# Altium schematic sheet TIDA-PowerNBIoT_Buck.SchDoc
size 431 x 279 mm; Date: Not shown in title block; ApprovedBy: Not shown in title block; CheckedBy: Not shown in title block; Author: Not shown in title block; CompanyName: Not shown in title block; DrawnBy: Chris Glaser; Engineer: Not shown in title block; Organization: Not shown in title block; Address1: Not shown in title block; Address2: Not shown in title block; Address3: Not shown in title block; Address4: Not shown in title block; DocumentNumber: 1; Revision: Use project parameter SCH_Rev; SheetNumber: 1; SheetTotal: 2; PageSetup: Record=PageOptions¦CenterHorizontal=True¦CenterVertical=True¦PrintScale=1.00¦XCorrection=1.00¦YCorrection=1.00¦PrintKind=0¦BorderSize=5000000¦LeftOffset=0¦BottomOffset=0¦Orientation=2¦PaperLength=1000¦PaperWidth=1000¦Scale=100¦PaperSource=15¦PrintQuality=600¦MediaType=1¦DitherType=10¦PaperKind=Letter¦PrintScaleMode=1
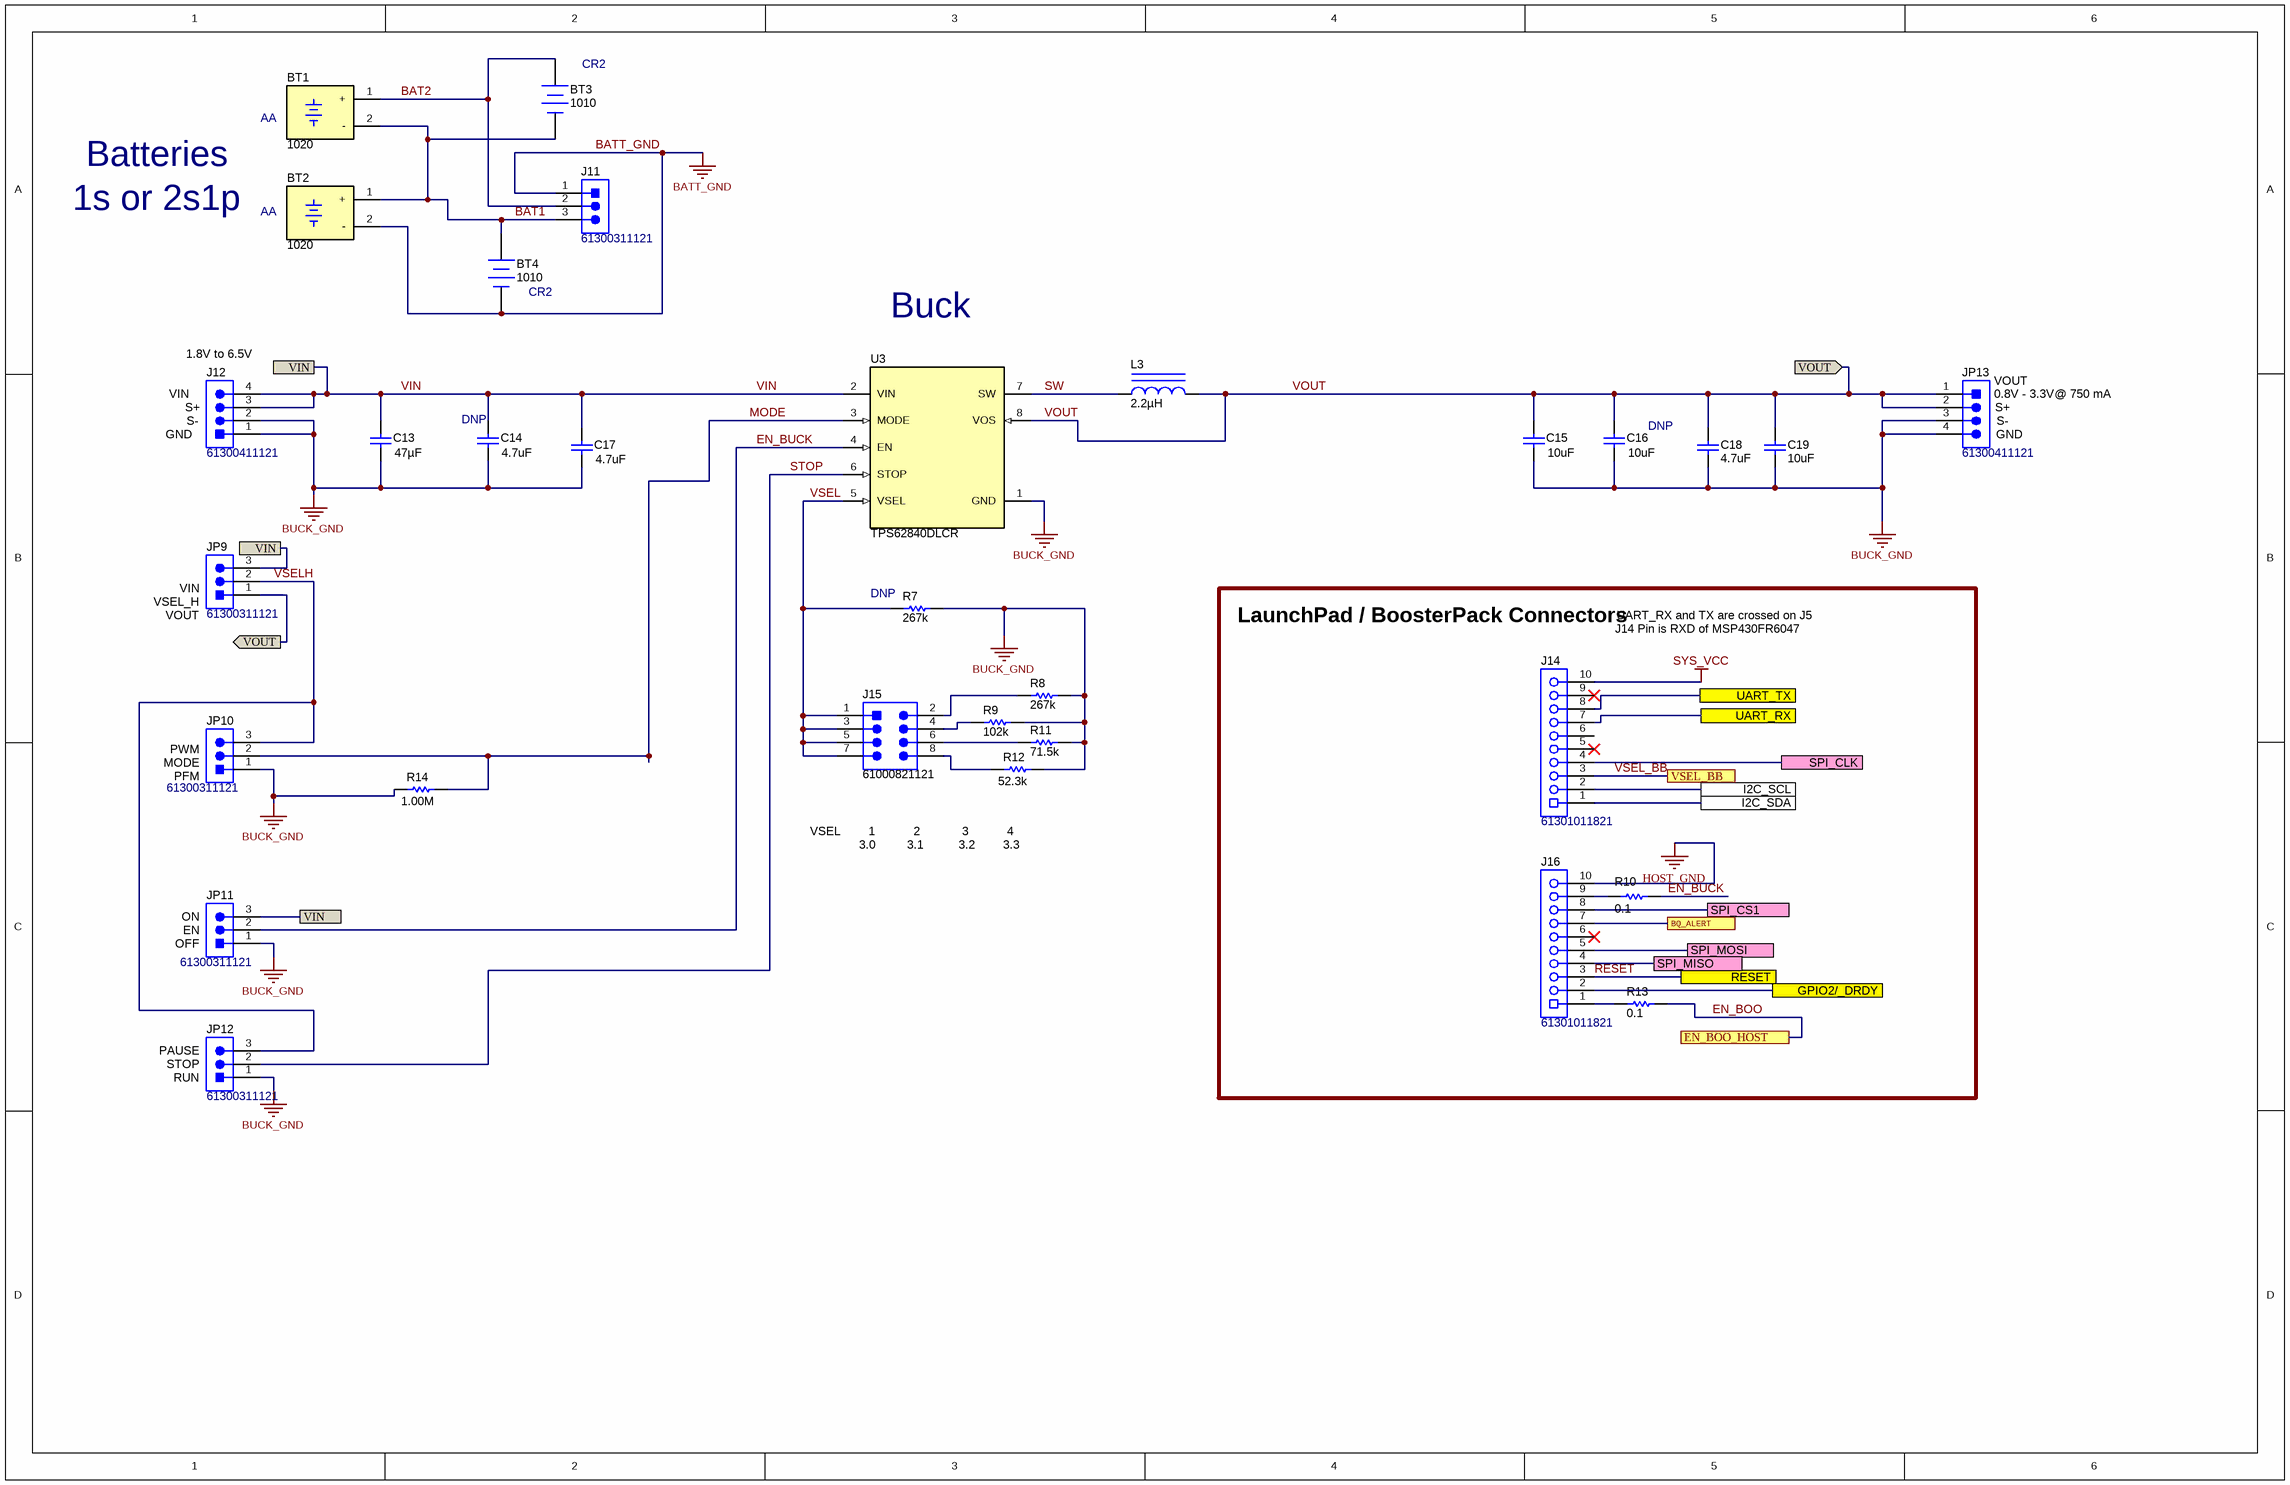
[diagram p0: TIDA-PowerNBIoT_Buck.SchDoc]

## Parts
BT1  1020  [Keystone_1020]
BT2  1020  [Keystone_1020]
BT3  1010  [BAT_1010]
BT4  1010  [BAT_1010]
C13  ValueDisplayed: 47µF  [0805_HV]  (hidden comment: GRM21BR61A476ME15L)
C14  ValueDisplayed: 4.7uF  [0402S]  (hidden comment: GRM155R61A475MEAAD)
C15  ValueDisplayed: 10uF  [0402_070]  (hidden comment: GRM155R60G106ME44D)
C16  ValueDisplayed: 10uF  [0402_070]  (hidden comment: GRM155R60G106ME44D)
C17  ValueDisplayed: 4.7uF  [0402S]  (hidden comment: GRM155R61A475MEAAD)
C18  ValueDisplayed: 4.7uF  [0603S]  (hidden comment: GRM188R60J475ME19D)
C19  ValueDisplayed: 10uF  [0805_HV]  (hidden comment: GRM21BR70J106KE76L)
J11  61300311121  [WURTH_61300311121]
J12  61300411121  [WURTH_61300411121]
J14  61301011821  [Wurth_61301011821]
J15  61000821121  [Wurth_61000821121]
J16  61301011821  [Wurth_61301011821]
JP9  61300311121  [WURTH_61300311121]
JP10  61300311121  [WURTH_61300311121]
JP11  61300311121  [WURTH_61300311121]
JP12  61300311121  [WURTH_61300311121]
JP13  61300411121  [WURTH_61300411121]
L3  ValueDisplayed: 2.2µH  [DFE201612E]  (hidden comment: DFE201612E-2R2M=P2)
R7  ValueDisplayed: 267k  [0402]  (hidden comment: ERJ-2RKF2673X)
R8  ValueDisplayed: 267k  [0402]  (hidden comment: ERJ-2RKF2673X)
R9  ValueDisplayed: 102k  [0402]  (hidden comment: CRCW0402102KFKED)
R10  ValueDisplayed: 0.1  [0402]  (hidden comment: ERJ-2BSFR10X)
R11  ValueDisplayed: 71.5k  [0402]  (hidden comment: CRCW040271K5FKED)
R12  ValueDisplayed: 52.3k  [0402]  (hidden comment: CRCW040252K3FKED)
R13  ValueDisplayed: 0.1  [0402]  (hidden comment: ERJ-2BSFR10X)
R14  ValueDisplayed: 1.00M  [0402]  (hidden comment: CRCW04021M00FKED)
U3  TPS62840DLCR  [DLC0008B]

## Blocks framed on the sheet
LaunchPad / BoosterPack Connectors: J14 J16 R10 R13

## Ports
BQ_ALERT, EN_BOO_HOST, GPIO2/_DRDY, I2C_SCL, I2C_SDA, RESET, SPI_CLK, SPI_CS1, SPI_MISO, SPI_MOSI, UART_RX, UART_TX, VIN, VOUT (in), VOUT (out), VSEL_BB

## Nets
BATT_GND: BT2.2(-) BT4.2(-) J11.1
BUCK_GND: C13.2 C14.2 C15.2 C16.2 C17.2 C18.2 C19.2 J12.1 J12.2 JP10.1 JP11.1 JP12.1 JP13.3 JP13.4 R7.2 R8.2 R9.2 R11.2 R12.2 R14.1 U3.1(GND)
HOST_GND: J16.10
SYS_VCC: J14.10
BAT1: BT1.2(-) BT2.1(+) BT3.2(-) BT4.1(+) J11.3
BAT2: BT1.1(+) BT3.1(+) J11.2
BQ_ALERT: J16.7 ; port BQ_ALERT
EN_BOO: R13.2 ; port EN_BOO_HOST
EN_BUCK: JP11.2 R10.2 U3.4(EN)
GPIO2/_DRDY: J16.2 ; port GPIO2/_DRDY
I2C_SCL: J14.2 ; port I2C_SCL
I2C_SDA: J14.1 ; port I2C_SDA
MODE: JP10.2 R14.2 U3.3(MODE)
RESET: J16.3 ; port RESET
SPI_CLK: J14.4 ; port SPI_CLK
SPI_CS1: J16.8 ; port SPI_CS1
SPI_MISO: J16.4 ; port SPI_MISO
SPI_MOSI: J16.5 ; port SPI_MOSI
STOP: JP12.2 U3.6(STOP)
SW: L3.1 U3.7(SW)
UART_RX: J14.7 ; port UART_RX
UART_TX: J14.8 ; port UART_TX
VIN: C13.1 C14.1 C17.1 J12.3 J12.4 JP9.3 JP11.3 U3.2(VIN) ; port VIN
VOUT: C15.1 C16.1 C18.1 C19.1 JP9.1 JP13.1 JP13.2 L3.2 U3.8(VOS) ; port VOUT
VSEL: J15.1 J15.3 J15.5 J15.7 R7.1 U3.5(VSEL)
VSEL_BB: J14.3 ; port VSEL_BB
VSELH: JP9.2 JP10.3 JP12.3
NetJ15_2: J15.2 R8.1
NetJ15_4: J15.4 R9.1
NetJ15_6: J15.6 R11.1
NetJ15_8: J15.8 R12.1
NetJ16_1: J16.1 R13.1
NetJ16_9: J16.9 R10.1

Not connected (* = marked no-connect by the designer): J14 5* 6 9*; J16 6*

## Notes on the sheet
- (near BT3) CR2
- AA
- 1s or 2s1p
- Batteries
- (near BT4) CR2
- (near J12) 1.8V to 6.5V
- Buck
- (near J12) VIN
- (near J12) GND
- (near J12) S+
- (near J12) S-
- (near C14) DNP
- DNP
- (near JP13) S+
- (near JP13) S-
- (near JP13) GND
- (near JP13) VOUT
- (near JP13) 0.8V - 3.3V
- @ 750 mA
- (near JP9) VSEL_H
- (near JP9) VOUT
- (near JP9) VIN
- (near R7) DNP
- J14 Pin is RXD of MSP430FR6047
- UART_RX and TX are crossed on J5
- (near JP10) MODE
- (near JP10) PWM
- (near JP10) PFM
- VSEL        1           2            3           4
  3.0         3.1          3.2        3.3
- (near JP11) OFF
- (near JP11) ON
- (near JP11) EN
- (near JP12) PAUSE
- (near JP12) STOP
- (near JP12) RUN

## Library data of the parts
BT1 BT2 = CMP-0003908-1: HOLDER BATTERY AAA, SMT; Manufacturer: Keystone; CompType: Battery Holder
BT3 BT4 = CMP-0003630-1: Battery Holder, Nylon, CR2, SMT; Manufacturer: Keystone
C13 = CMP-0078699-1: CAP, CERM, 47 µF, 10 V,+/- 20%, X5R, 0805; Manufacturer: MuRata; TaMin_C: -55°C; Polarized: N; Green_Lifecycle: Active; SizeAreaWB_mm2: 6.75; Green_REACh: Passed; U/M: EA; Value: 47uF; TaMax_C: 85°C; SizeZ_mm: 1.45; SizeX_mm: 2; SizeY_mm: 1.25; Cap_Case: 0805; Value2: 10V; SizeArea_mm2: 2.5; CompType: Capacitor; AEC Category: Q200
C14 C17 = CMP-0006582-2: CAP, CERM, 4.7 uF, 10 V, +/- 20%, X5R, 0402; Manufacturer: MuRata; TaMin_C: -55°C; Polarized: N; SizeAreaWB_mm2: 3; Value1: Unknown; U/M: EA; Value: 4.7uF; TaMax_C: 85°C; SizeZ_mm: 0.6; SizeX_mm: 1; SizeY_mm: 0.5; Cap_Case: 0402; Value2: 10V; CompType: Capacitor; Cap_F: 4.7µF; AEC Category: Q200
C15 C16 = CMP-0006528-2: CAP, CERM, 10 uF, 4 V, +/- 20%, X5R, 0402; Manufacturer: MuRata; TaMin_C: -55°C; Polarized: N; SizeAreaWB_mm2: 3; Value1: Unknown; U/M: EA; Value: 10uF; TaMax_C: 85°C; SizeZ_mm: 0.7; SizeX_mm: 1; SizeY_mm: 0.5; Cap_Case: 0402; Value2: 4V; Cap_F: 10µF; AEC Category: Q200
C18 = CMP-0007312-5: CAP, CERM, 4.7 uF, 6.3 V, +/- 20%, X5R, 0603; Manufacturer: MuRata; Polarized: N; CompType: Capacitor; Value: 4.7uF; U/M: EA; Cap_F: 4.7µF; ESR_ohm: 1m; Value1: 0.001 ohm; VDC_V: 6.3V; TaMin_C: -55°C; TaMax_C: 85°C; Cap_Case: 0603; SizeArea_mm2: 1.28; SizeAreaWB_mm2: 4.68; SizeX_mm: 1.6; SizeY_mm: 0.8; SizeZ_mm: 1; AEC Category: Q200
C19 = CMP-0008311-2: CAP, CERM, 10 uF, 6.3 V, +/- 10%, X7R, 0805; Manufacturer: MuRata; Polarized: N; Value: 10uF; U/M: EA; Cap_F: 10µF; Value1: Unknown; VDC_V: 6.3V; TaMin_C: -55°C; TaMax_C: 125°C; Cap_Case: 0805; SizeArea_mm2: 2.5; SizeAreaWB_mm2: 6.75; SizeX_mm: 2; SizeY_mm: 1.25; SizeZ_mm: 1.45; AEC Category: Q200
J11 JP9-JP12 = CMP-0054796-2: Header, 2.54 mm, 3x1, Gold, TH; Manufacturer: Wurth Elektronik; Pitch_mm: 2.54; Green_Lifecycle: Active; Cert_UL: Y; Shrouded: N; Green_REACh: Passed; Gender: Male; Row_Count: 1
J12 JP13 = CMP-0054798-2: Header, 2.54 mm, 4x1, Gold, TH; Manufacturer: Wurth Elektronik; Pitch_mm: 2.54; Gender: Male; Row_Count: 1; Cert_UL: Y; Shrouded: N
J14 J16 = CMP-0054762-1: Receptacle, 2.54mm, 10x1, Gold, TH; Manufacturer: Wurth Elektronik; CNHeader: FALSE; Current_A: 3A; Gender: Female; Cert_CSA: Y; Voltage_V: 250V; Row_Count: 1; Pitch_mm: 2.54
J15 = CMP-0079535-2: Header, 2.54mm, 4x2, Gold, SMT; Manufacturer: Wurth Elektronik; Pitch_mm: 2.54; Gender: Male; Cert_UL: Y; Current_A: 3A; Voltage_V: 250V; Shrouded: N; Row_Count: 2
L3 = CMP-0080775-1: Inductor, Shielded, Metal Composite, 2.2 µH, 1.8 A, 0.116 ohm, SMD; Manufacturer: MuRata; Isat: 2.4A @ 30% inductance drop; Irms: 1.8A @ 40C rise; SizeAreaWB_mm2: 7.8; DCR_ohm: 1.16d; Value: 2.2uH; Imax_A: 1.8A; SizeZ_mm: 1.2; SizeX_mm: 2; SizeY_mm: 1.6; SizeArea_mm2: 3.2; AEC Qualified: N; AEC Category: Q200
R7 R8 = CMP-0026690-1: RES, 267 k, 1%, 0.1 W, AEC-Q200 Grade 0, 0402; Manufacturer: Panasonic; Power_W: 100mW; TempCo: 100 ppm/C; U/M: EA; Value: 267k; EIA_Code: E96; SizeX_mm: 1; SizeY_mm: 0.5; SizeZ_mm: 0.6; Value2: 0.1W; AEC Qualified: Y; VDC_V: 50V; AEC Grade: 0; AEC Category: Q200
R9 = CMP-0025952-1: RES, 102 k, 1%, 0.063 W, 0402; Manufacturer: Vishay-Dale; Power_W: 63mW; TempCo: 100 ppm/C; U/M: EA; Value: 102k; EIA_Code: E96; SizeX_mm: 1; SizeY_mm: 0.5; SizeZ_mm: 0.6; Value2: 0.063W; VDC_V: 50V; AEC Category: Q200
R10 R13 = CMP-0026647-2: RES, 0.1, 1%, 0.125 W, AEC-Q200 Grade 0, 0402; Manufacturer: Panasonic; Power_W: 125mW; TempCo: 300 ppm/C; Value_Code: R100; Value: 0.1; EIA_Code: E96; SizeX_mm: 1; SizeY_mm: 0.5; SizeZ_mm: 0.6; Value2: 0.125W; AEC Qualified: Y; AEC Category: Q200; AEC Grade: 0; SizeAreaWB_mm2: 3
R11 = CMP-0026535-2: RES, 71.5 k, 1%, 0.063 W, AEC-Q200 Grade 0, 0402; Manufacturer: Vishay-Dale; Power_W: 63mW; TempCo: 100 ppm/C; Value_Code: 71k5; Value: 71.5k; EIA_Code: E96; SizeX_mm: 1; SizeY_mm: 0.5; SizeZ_mm: 0.6; Value2: 0.063W; AEC Qualified: Y; VDC_V: 50V; AEC Category: Q200; AEC Grade: 0
R12 = CMP-0026441-2: RES, 52.3 k, 1%, 0.063 W, AEC-Q200 Grade 0, 0402; Manufacturer: Vishay-Dale; Power_W: 63mW; TempCo: 100 ppm/C; Value_Code: 52k3; Value: 52.3k; EIA_Code: E96; SizeX_mm: 1; SizeY_mm: 0.5; SizeZ_mm: 0.6; Value2: 0.063W; AEC Qualified: Y; VDC_V: 50V; AEC Category: Q200; AEC Grade: 0
R14 = CMP-0026100-2: RES, 1.00 M, 1%, 0.063 W, AEC-Q200 Grade 0, 0402; Manufacturer: Vishay-Dale; Power_W: 63mW; TempCo: 100 ppm/C; Value_Code: 1M00; Value: 1.00Meg; EIA_Code: E96; Res_ohm: 1M; SizeX_mm: 1; SizeY_mm: 0.5; SizeZ_mm: 0.6; Value2: 0.063W; AEC Qualified: Y; VDC_V: 50V; AEC Category: Q200; AEC Grade: 0
U3 = CMP-0081431-3: Ultra low IQ Step Down Converter, DLC0008A (VSON-HR-8); Alternate Manufacturer: Texas Instruments; SizeAreaWB_mm2: 7.5; SizeZ_mm: 1; SizeX_mm: 1.5; SizeY_mm: 2; SizeArea_mm2: 3; CompType: IC; AEC Qualified: N; AEC Category: Q200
